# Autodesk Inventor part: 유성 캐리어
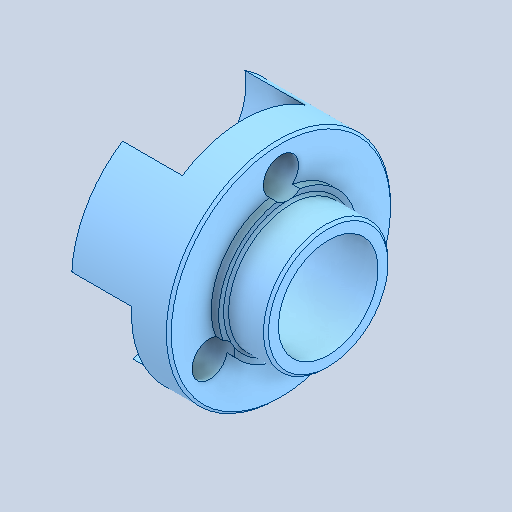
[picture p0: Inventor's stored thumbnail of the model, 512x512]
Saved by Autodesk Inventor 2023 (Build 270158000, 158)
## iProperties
Created: 2026-05
Part Number: 유성 캐리어
Material: 강철, 탄소
Document SubType Name: Modeling
Designer: home
Density: 7.85 g/cm^3
Appearance: 기본값
Author: jhkim
Sending System: Autodesk Inventor 2027
Preprocessor: ST-DEVELOPER v20.1
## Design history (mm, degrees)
feature "솔리드1"
node "솔리드2"
